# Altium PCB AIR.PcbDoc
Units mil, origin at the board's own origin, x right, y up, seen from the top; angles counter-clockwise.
Board outline 2440 x 700 mil, 2 copper layers (Top Layer, Bottom Layer); 70 components, 62 nets, 272 pads, 280 vias.
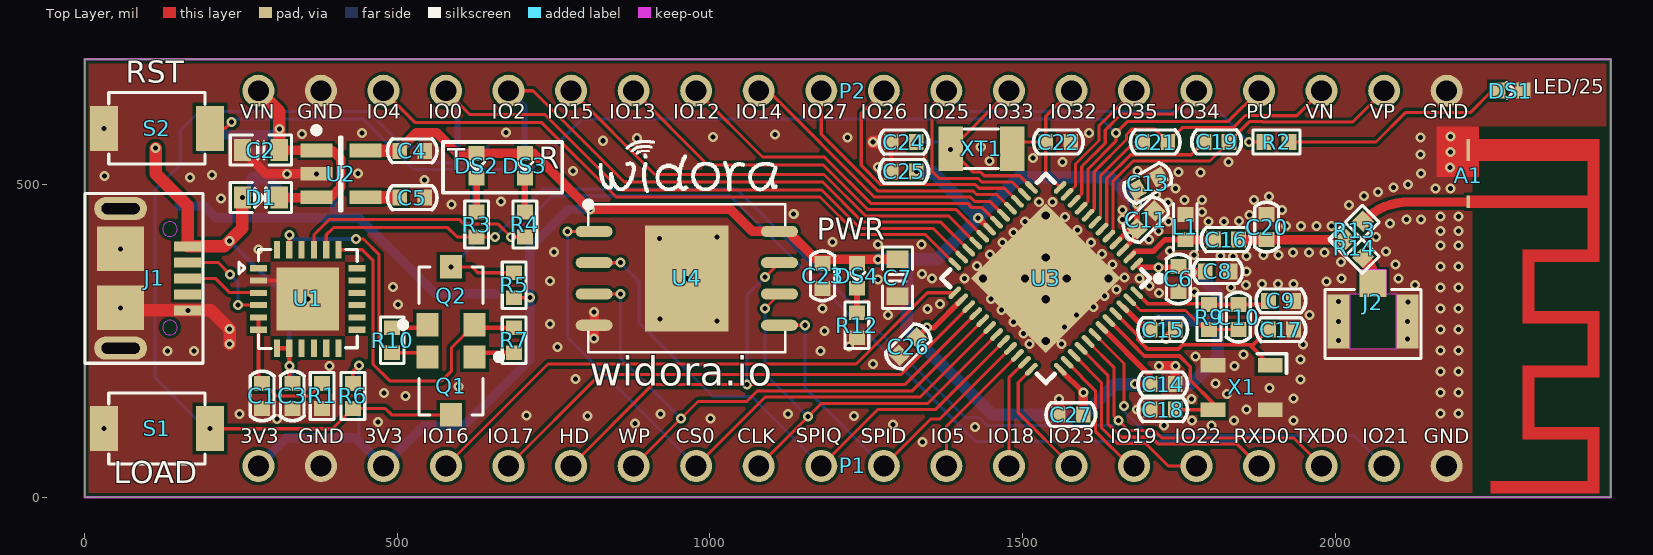
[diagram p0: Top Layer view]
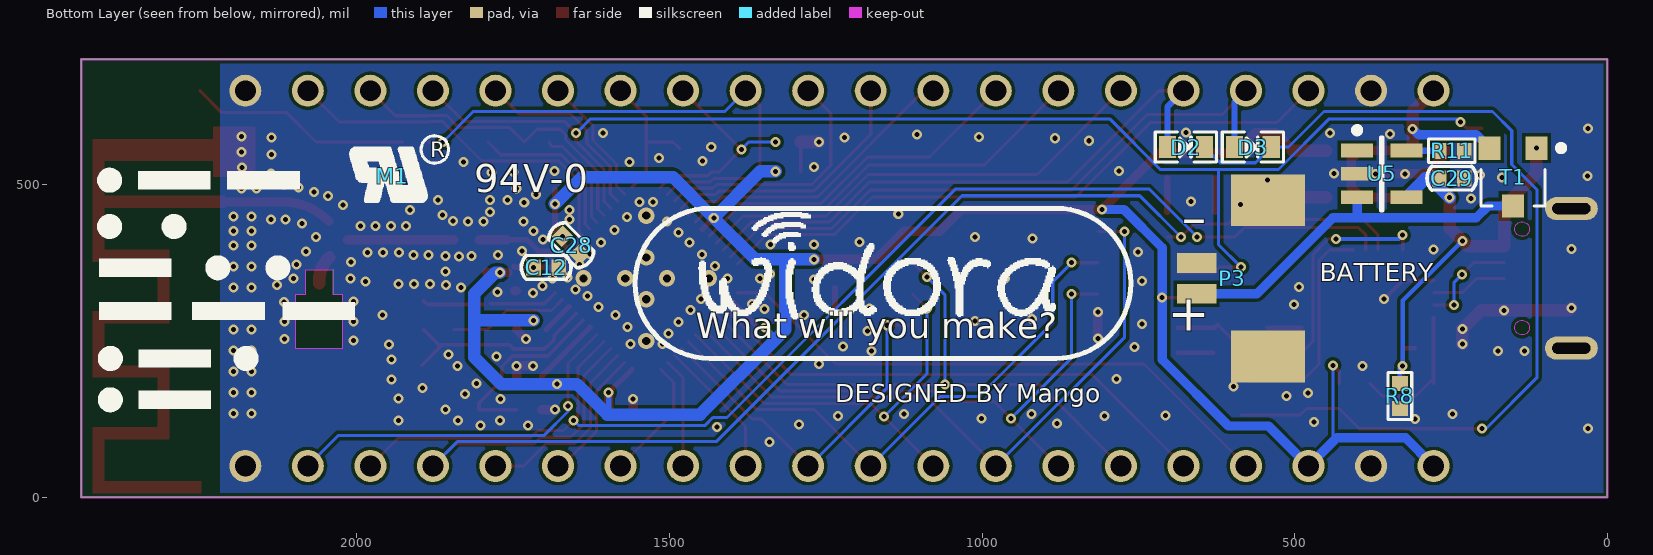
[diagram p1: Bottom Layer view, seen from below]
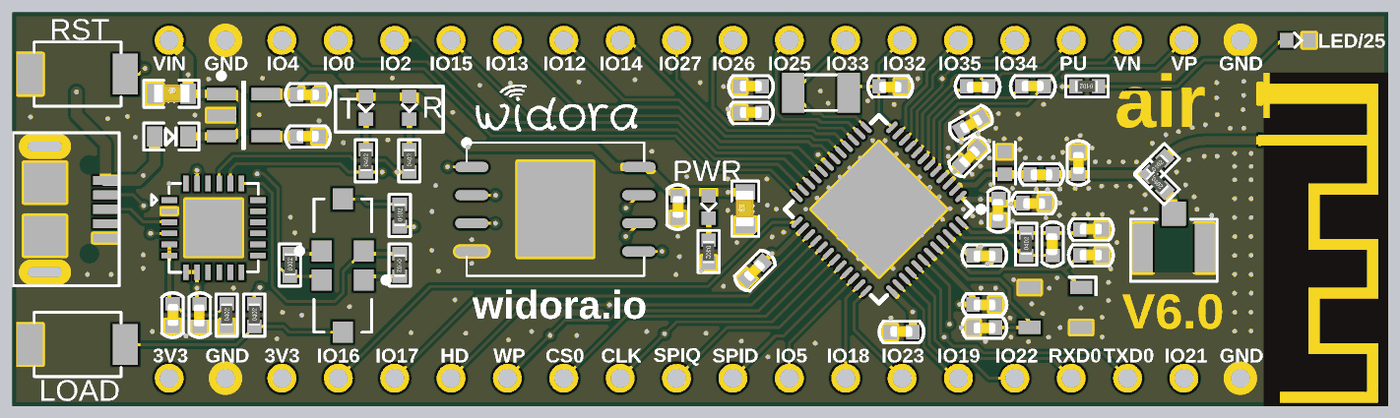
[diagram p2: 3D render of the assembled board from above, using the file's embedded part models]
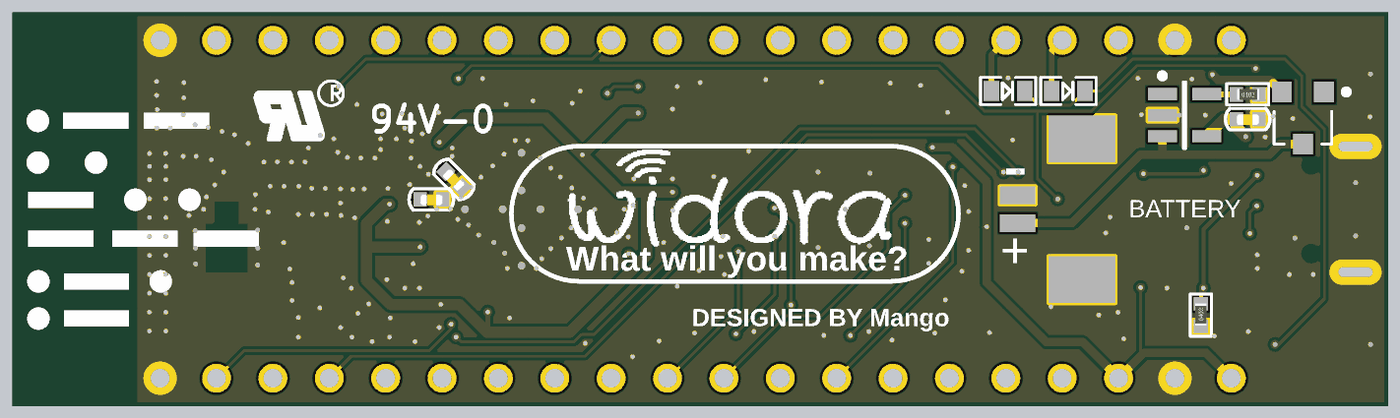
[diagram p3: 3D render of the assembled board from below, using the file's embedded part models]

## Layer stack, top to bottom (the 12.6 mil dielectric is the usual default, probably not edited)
Top Solder: solder mask 0.4, Solder Resist, Dk 3.5
Top Layer: signal copper 1.4
Dielectric1: dielectric 12.6, FR-4, Dk 4.8
Bottom Layer: signal copper 1.4
Bottom Solder: solder mask 0.4, Solder Resist, Dk 3.5

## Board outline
0,0 2440,0 2440,700 0,700

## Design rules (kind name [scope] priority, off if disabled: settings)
Clearance Clearance_1 [InPolygon] p1: gap=5
Clearance [All] p2: gap=5
ComponentClearance [All] p1 off: gap=10 collisioncheckmode=3 verticalgap=10 showdistances=FALSE
DiffPairsRouting [All] p1: maxlimit=10 minlimit=10 mostfreqgap=10 toplayer_minwidth=15 toplayer_maxwidth=15 toplayer_prefwidth=15 bottomlayer_minwidth=15 bottomlayer_maxwidth=15 bottomlayer_prefwidth=15 maxuncoupledlength=500
FabricationTestPointUsage TestPointUsage [All] p1 off: valid=0 allowmultiple=FALSE
FabricationTestpoint Testpoint [All] p1 off: side=3 testpointundercomponent=TRUE minsize=40 maxsize=100 preferedsize=60 minholesize=0 maxholesize=40 preferedholesize=32 testpointgrid=1 allowsidetop=TRUE allowsidebottom=TRUE usegrid=TRUE gridtolerance=0.01
Height [All] p1 off: minheight=0 maxheight=1000 prefheight=500
HoleToHoleClearance [All] p1: gap=6 allowstackedmicrovias=TRUE
MinimumSolderMaskSliver [All] p1: minsoldermaskwidth=1
NetAntennae [All] p1: netantennaetolerance=4
PlaneConnect [All] p1: planeconnectstyle=Direct reliefexpansion=20 reliefentries=4 reliefconductorwidth=10 reliefairgap=10
PolygonConnect [All] p1: connectstyle=Direct reliefconductorwidth=10 reliefentries=4 polygonreliefangle="90 Angle" airgapwidth=10
RoutingVias [All] p1: holewidth=8 width=16 viastyle="Through Hole" minholewidth=8 minwidth=16 maxholewidth=28 maxwidth=50
SilkToSilkClearance [All] p1: silktosilkclearance=0
SilkToSolderMaskClearance SilkscreenOverComponentPads [IsPad] p1: minsilkscreentomaskgap=0 clearancetoexposedcopper=TRUE
SolderMaskExpansion [All] p1: expansion=4
Width [All] p1: maxlimit=30 minlimit=5 preferedwidth=6
18 further rules are at their usual default settings.

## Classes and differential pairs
differential pair U: +U_P -U_N

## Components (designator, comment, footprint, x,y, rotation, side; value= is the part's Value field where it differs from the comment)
A1 "WIFI天线" 2.4G 2210,573 r270 top locked
C1 "1uF" C0402 284.02,162 r270 top
C2 "4.7uF" C0603 282,555 r0 top
C3 "1uF" C0402 332.22,162 r90 top
C4 "0.1uF" C0402 524,554 r180 top
C5 "470pF" C0402 524,479 r0 top
C6 "100pF" C0402 1749,349 r90 top
C7 "4.7uF" C0603 1300,350.94 r90 top
C8 "0.1uF" C0402 1812,361 r180 top
C9 "10nF" C0402 1913,314 r0 top
C10 "3nF" C0402 1845,288 r90 top
C11 "100pF" C0402 1697.05,443.68 r225 top
C12 "0.1uF" C0402 1697,367.5 r0 bottom
C13 "1uF" C0402 1700,502 r210 top
C14 "0.1uF" C0402 1724,181 r180 top locked
C15 "100pF" C0402 1724,267.96 r180 top
C16 "6.9pF" C0402 1825,412 r180 top
C17 "15pF" C0402 1913,268 r0 top
C18 "15pF" C0402 1724,140 r180 top locked
C19 "270pF" C0402 1810,568.04 r0 top
C20 "2.4pF" C0402 1890,432 r270 top
C21 "270pF" C0402 1712,568 r180 top
C22 "15pF" C0402 1557,568 r180 top
C23 "0.1uF" C0402 1180,353.94 r270 top
C24 "15pF" C0402 1310,568 r0 top
C25 "0.1uF" C0402 1310,521 r0 top
C26 "0.1uF" C0402 1317,241 r45 top
C27 "0.1uF" C0402 1577,132 r0 top
C28 "0.1uF" C0402 1657,403 r45 bottom
C29 "0.1uF" C0402 249,510 r0 bottom
D1 "1N5819 0603" SOD523 282,479 r0 top
D2 "1N5819 0603" SOD523 674,560 r180 bottom
D3 "1N5819 0603" SOD523 567,560 r180 bottom
DS1 "BLUE" LED0402 2280,650 r0 top
DS2 "YELLOW" LED0402 627,530 r270 top
DS3 "GREEN" LED0402 704,530 r270 top
DS4 "BLUE" LED0402 1235,354 r270 top
J1 "MK5P microUSB" MICROUSB 95,350 r270 top locked
J2 "ipex" "I-PEX SOCKET" 2060,281 r180 top locked
L1 "1.6nH" L0402 1760,432 r270 top
M1 "mark" ZY_UR-3X2 1943,513 r180 bottom locked
P1 "Header 20" HDR1X20-M2 278,50 r0 top locked
P2 "Header 20" HDR1X20-M2 278,650 r0 top locked
P3 "BATT" PH1.25-T 657,350 r90 bottom locked
Q1 "9014" SOT23 586,178 r180 top
Q2 "9014" SOT23 586,322 r0 top locked
R1 "1K" R0402 380,162 r90 top
R2 "5.1K" R0402 1906,568.02 r180 top
R3 "5.1K" R0402 627,436 r90 top
R4 "5.1K" R0402 704,436 r90 top
R5 "5.1K" R0402 687,339 r90 top
R6 "5.1K" R0402 429,162 r90 top
R7 "5.1K" R0402 687,251 r270 top
R8 "5.1K" R0402 332,162 r90 bottom
R9 "20K" R0402 1798,288 r90 top
R10 "5.1K" R0402 492,251 r90 top
R11 "3.3K" R0402 249,554 r180 bottom
R12 "5.1K" R0402 1235,275 r270 top
R13 "0R" R0402 2030.05,426.81 r45 top locked
R14 "0R" R0402 2030,398 r315 top locked
S1 "SW-BUTTON" MINIBUTTON 116,110 r180 top locked
S2 "SW-BUTTON" MINIBUTTON 116,590 r180 top locked
T1 "AO3401" SOT23 151,512 r0 bottom
U1 "CP2104" QFN24 357,317 r0 top locked
U2 "MIC5219-3.3" SOT23-5 410,517 r0 top
U3 "ESP32" QFN40P600X600X100-48N 1537,350 r225 top locked
U4 "W25Q32" WSON-SPIFLASH 963,350 r0 top locked
U5 "LTC4054" SOT23-5 361,517 r180 bottom
X1 "40MHz-3225" XTAL3225 1850,176 r0 top locked
XT1 "32.768K-3215" Y3215 1434,557 r0 top

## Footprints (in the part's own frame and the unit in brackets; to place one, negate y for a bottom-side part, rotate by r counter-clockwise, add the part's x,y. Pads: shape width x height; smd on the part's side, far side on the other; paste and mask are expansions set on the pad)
2.4G [mil]
  rect 20x5 smd paste-39.37: 1(100.4,2.5)
  rect 35.43x5 smd paste-39.37: 2(17.72,2.5)
  Top Layer region: 0,0 35.43,0 35.43,194.88 0,194.88
  Top Layer region: 90.55,0 110.24,0 110.24,194.88 90.55,194.88
  Top Layer region: 547.24,37.79 566.93,37.79 566.93,194.88 547.24,194.88
  Top Layer region: 460.63,193.04 566.93,193.04 566.93,212.72 460.63,212.72
  Top Layer region: 460.63,88.98 480.31,88.98 480.31,194.88 460.63,194.88
  Top Layer region: 379.92,88.98 462.6,88.98 462.6,108.66 379.92,108.66
  Top Layer region: 362.2,88.98 381.89,88.98 381.89,194.88 362.2,194.88
  Top Layer region: 275.59,193.04 381.89,193.04 381.89,212.72 275.59,212.72
  Top Layer region: 275.59,88.98 295.28,88.98 295.28,194.88 275.59,194.88
  Top Layer region: 194.88,89.1 277.56,89.1 277.56,108.78 194.88,108.78
  Top Layer region: 177.16,88.98 196.85,88.98 196.85,194.88 177.16,194.88
  Top Layer region: 0.12,192.91 196.97,192.91 196.97,212.6 0.12,212.6
C0402 [mm]
  rect 0.6x0.65 smd: 1(-0.508,0) 2(0.508,0)
  silkscreen extent -1.01,-0.48 1.01,0.48, body extent -0.51,-0.23 0.49,0.27, height 0.5
C0603 [mm]
  rect 0.7x0.9 smd: 1(-0.75,0) 2(0.75,0)
  silkscreen extent -1.24,-0.61 1.24,0.61, body extent -0.79,-0.38 0.81,0.42, height 0.3
HDR1X20-M2 [mm]
  round 1.3 hole 0.85: 1(0,0) 2(2.54,0) 3(5.08,0) 4(7.62,0) 5(10.16,0) 6(12.7,0) 7(15.24,0) 8(17.78,0) 9(20.32,0) 10(22.86,0) 11(25.4,0) 12(27.94,0) 13(30.48,0) 14(33.02,0) 15(35.56,0) 16(38.1,0) 17(40.64,0) 18(43.18,0) 19(45.72,0) 20(48.26,0)
"I-PEX SOCKET" [mm]
  rect 1.1x1.1 smd: 1(0,-1.55)
  rect 0.9x2.2 smd: 2(1.4,0) 3(-1.4,0)
  Keep-Out Layer pour cut-out: -0.95,1.1 -0.95,-1.101 -0.551,-1.101 -0.551,-2.101 0.001,-2.101 0.55,-2.101 0.55,-1.101 0.95,-1.101 0.95,1.1
  silkscreen extent -1.95,-1.3 1.95,1.5
L0402 [mm]
  rect 0.6x0.65 smd: 1(-0.508,0) 2(0.508,0)
  silkscreen extent -0.95,-0.48 0.95,0.48
LED0402 [mm]
  rect 0.6x0.65 smd: A(-0.508,0) K(0.508,0)
  silkscreen extent -0.15,-0.32 0.18,0.33
MICROUSB [mm] "MICROUSB"
  rect 0.4x1.1 smd: 1(-1.3,1.78) 2(-0.65,1.78) 3(0,1.78) 4(0.65,1.78) 5(1.3,1.78)
  oval 0.94x2.15 hole 0.45 slot 1.55 at 90 deg: 6(-2.835,-0.946) 7(2.835,-0.946)
  rect 1.8x1.9 smd: 8(-1.2,-0.946) 9(1.2,-0.946)
  Keep-Out Layer circle w0.025: c-2,1.054 r0.3
  Keep-Out Layer circle w0.025: c2,1.054 r0.3
  silkscreen extent -3.45,-2.4 3.45,2.4
MINIBUTTON [mil] "MINIBUTTON"
  rect 44.88x72.05 smd: 1(-84.42,0.08) 2(84.88,0.08)
  silkscreen extent -77,-57 77,57
PH1.25-T [mm] "2.0 tie"
  rect 2.1x3 smd: 0(-3.175,-2.9) 0(3.175,-2.9)
  rect 0.8x1.6 smd: 1(0.625,0) 2(-0.625,0)
QFN24 [mm]
  rect 0.7x0.25 smd: 1(-2,1.25) 2(-2,0.75) 3(-2,0.25) 4(-2,-0.25) 5(-2,-0.75) 6(-2,-1.25) 13(2,-1.25) 14(2,-0.75) 15(2,-0.25) 16(2,0.25) 17(2,0.75) 18(2,1.25)
  rect 0.25x0.7 smd: 7(-1.25,-2) 8(-0.75,-2) 9(-0.25,-2) 10(0.25,-2) 11(0.75,-2) 12(1.25,-2) 19(1.25,2) 20(0.75,2) 21(0.25,2) 22(-0.25,2) 23(-0.75,2) 24(-1.25,2)
  rect 2.55x2.55 smd: 25(0,0)
  silkscreen extent -2.79,-2.01 2.01,2.01
QFN40P600X600X100-48N [mm] "QFN, 48-Leads, Body 6.0x6.0mm (max), Pitch 0.40mm, IPC Medium Density"
  oval 0.65x0.2 smd: 1(-3.025,2.2) 2(-3.025,1.8) 3(-3.025,1.4) 4(-3.025,1) 5(-3.025,0.6) 6(-3.025,0.2) 7(-3.025,-0.2) 8(-3.025,-0.6) 9(-3.025,-1) 10(-3.025,-1.4) 11(-3.025,-1.8) 12(-3.025,-2.2) 25(3.025,-2.2) 26(3.025,-1.8) 27(3.025,-1.4) 28(3.025,-1) 29(3.025,-0.6) 30(3.025,-0.2) 31(3.025,0.2) 32(3.025,0.6) 33(3.025,1) 34(3.025,1.4) 35(3.025,1.8) 36(3.025,2.2)
  oval 0.2x0.65 smd: 13(-2.2,-3.025) 14(-1.8,-3.025) 15(-1.4,-3.025) 16(-1,-3.025) 17(-0.6,-3.025) 18(-0.2,-3.025) 19(0.2,-3.025) 20(0.6,-3.025) 21(1,-3.025) 22(1.4,-3.025) 23(1.8,-3.025) 24(2.2,-3.025) 37(2.2,3.025) 38(1.8,3.025) 39(1.4,3.025) 40(1,3.025) 41(0.6,3.025) 42(0.2,3.025) 43(-0.2,3.025) 44(-0.6,3.025) 45(-1,3.025) 46(-1.4,3.025) 47(-1.8,3.025) 48(-2.2,3.025)
  rect 4.3x4.3 smd: 49(0,0)
  silkscreen extent -3.37,-3 3,3.38, body extent -3,-3 3,3, height 1
R0402 [mm]
  rect 0.6x0.65 smd: 1(-0.508,0) 2(0.508,0)
  silkscreen extent -0.95,-0.48 0.95,0.48, body extent -0.47,-0.25 0.53,0.25, height 0.35
SOD523 [mm]
  rect 0.7x0.9 smd: A(-0.75,0) K(0.75,0)
  silkscreen extent -1.24,-0.61 1.24,0.61
SOT23 [mm] "SOT-23; 3 Leads; Body 3.0 x 2.5 mm, inc. leads (LxW max)"
  rect 0.9x0.95 smd: 1(-0.95,-1.175) 2(0.95,-1.175) 3(0,1.175)
  silkscreen extent -2.07,-1.3 1.3,1.18
SOT23-5 [mm] "SOT23, 5-Leads, Body 3.0x2.6mm (max), Pitch 0.95mm, IPC Medium Density"
  rect 1.3x0.55 smd: 1(-1,0.95) 2(-1,0) 3(-1,-0.95) 4(1,-0.95) 5(1,0.95)
  silkscreen extent -1.12,-1.5 0.05,1.9, body extent -0.7,-1.5 0.7,1.5, height 1.1
WSON-SPIFLASH [mm]
  oval 1.5x0.45 smd: 1(-3.764,1.905) 2(-3.764,0.635) 3(-3.764,-0.635) 4(-3.764,-1.905) 5(3.764,-1.905) 6(3.764,-0.635) 7(3.764,0.635) 8(3.764,1.905)
  rect 3.4x4.3 smd: 4(0,0)
  silkscreen extent -4.12,-3 4,3.12
XTAL3225 [mm] "XTAL3225"
  rect 1x0.6 smd: 1(1.16,0.887) 2(-1.16,0.887) 3(-1.16,-0.913) 4(1.16,-0.913)
  silkscreen extent 0.64,0.57 1.83,1.36
Y3215 [mm]
  rect 1x1.8 smd: 1(-1.25,0) 2(1.25,0)
  silkscreen extent -0.7,-0.8 0.7,0.8
ZY_UR-3X2 [mil]
  silkscreen extent -67,-40 90,65

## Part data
A1: library part ANT2.4G
C1 C2 C3 C4 C5 C6 C7 C8 C9 C10 C11 C12 C13 C14 C15 C17 C18 C19 C21 C22 C23 C24 C25 C26 C27 C28 C29: library part CAP, "普通小电容"
C16 C20: library part CAP, "射频电容"
D1 D2 D3: library part Diode, "普通二极管"
DS1 DS2 DS3 DS4: library part LED, "LED"
J1: library part MICRO_USB, "4固定脚microUSB座"
J2: library part MCX_IPEX
L1: library part L0402, "射频电感"
P1 P2: "Header, 20-Pin"
P3: library part "Header 2T", "Header, 4-Pin"
Q1 Q2: library part NPN, "NPN三极管"
R1 R2 R3 R4 R5 R6 R7 R8 R9 R10 R11 R12 R13 R14: library part RES, "普通电阻"
T1: library part MOS-P
U2: library part MIC5219
U4: library part SPIFLASH_SOP8W
U5: "锂电池管理芯片"
X1: library part XTAL3225
XT1: library part XT, "晶振"

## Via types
v1: diameter 16, hole 8, Top Layer to Bottom Layer, tented both sides, 272 vias
v2: diameter 25.98, hole 12.99, Top Layer to Bottom Layer, tented both sides, 8 vias

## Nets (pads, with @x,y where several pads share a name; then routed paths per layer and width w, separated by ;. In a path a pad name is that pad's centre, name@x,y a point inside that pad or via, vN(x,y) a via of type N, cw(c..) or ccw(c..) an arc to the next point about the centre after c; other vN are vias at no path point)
CHIP_PU: P2.17 Q2.3 R5.2 S2.1 U3.9 | length 2207.3
  Top Layer w5: S2.1 224.92,589.92 v1(235,600) ; v1(586,368.26) 619.46,368.26 628.72,359 R5.2 ; U3.9 1604.48,473.16 1604.48,524.62 1649,569.14 v1(1649,582) 1668,601 1829,601 P2.17
  Bottom Layer w5: v1(235,600) 236,600 241,605 445,605 526,524 622,524 ; v1(586,368.26) 586.34,368.26 622,403.92 622,524 ; v1(1649,582) 1626,605 796,605 715,524 622,524
DL: D2.K D3.K Q1.3 R6.1 S1.1 | length 1484.6
  Top Layer w5: v1(200.42,109.92) 200.84,109.5 396.5,109.5 R6.1 480.74,142 491,131.74 Q1.3
  Bottom Layer w5: v1(200.42,109.92) 194.08,109.92 113,191 113,492 153,532 153,586 183.74,616.74 453.26,616.74 510,560 D3.K 562.69,534.78 619.26,534.78 D2.K
DTR: Q1.2 R10.1 U1.23 | length 403.5
  Top Layer w5: v1(434,413) 446,413 471,388 471,249 R10.1@489,231 ; R10.1 541.86,231 Q1.2
  Top Layer w6: U1.23 v1(327.47,419)
  Bottom Layer w6: v1(327.47,419) 333.47,413 v1(434,413)
GND: A1.2 C1.2 C2.1 C3.1 C4.1 C5.2 C6.1 C7.1 C8.1 C9.2 C11.1 C12.1 C13.1 C14.1 C15.1 C17.2 C18.2 C20.1 C22.1 C23.2 C24.1 C25.1 C26.1 C27.1 C28.1 C29.1 DS1.K J1.5 J1.6 J1.7 J1.8 J1.9 J2.2 J2.3 L1.1 P1.2 P1.20 P2.2 P2.20 P3.0 P3.1 R1.1 R8.1 R11.2 R12.2 S1.2 S2.2 U1.2 U1.25 U2.2 U3.49 U4.4 U5.2 X1.2 X1.4 | length 682.6
  Top Layer w6: C25.1 C24.1 ; v1(1347.59,301) v1@1352,301
  Top Layer w7: U1.2 327.47,346.53 v1(357,317)
  Top Layer w15: C2.1 290.47,517 v1(370.63,517) ; v1(814.81,254) 814.81,275 v1(814.81,296) ; C27.1@1558,133 v1(1558,157) ; v1(1683,140) C18.2 ; v1(1718,210) v1(1744,210) C14.1 ; v1(1729.32,253.27) C15.1 ; C6.1@1744.72,330 C6.1@1747,330
  Top Layer w20: v1(57.74,302.75) 61.39,299.1 164.8,299.1 v1(165.09,298.81) 202.19,298.81 v1(232,269) v1(232,245) ; v1(1261,568) C24.1
  other v1: 1340,88 31.12,109.92 1424,112 1726,115 1802,115 1293,116 880,118 469,120 1771,123 1838,123 1933,123 308,125 1001,126 804,130 1230,130 707,131 248,133 921,133 1125,133 2168,133.6 2197,133.6 1858,140 1770,157 1933,158 513,162 1827,165 479,167 2168,167.2 2197,167.2 1895,175 598,177 1808,182 1944,188 785,189 2168,200.8 2197,200.8 392,210 1839,210 1261,213 1944,220 1776,225 1853,228 133,234 175,234 1177,234 2168,234.4 2197,234.4 756,240 1222,241 1948,244 1511,245 1562,245 2005,251 2115,253 1501,262 1183,266 2168,268 2197,268 1567,272 744,277 1485,280 2004.88,281 2115.12,281 1011,282 920,285 1285,291 1586,291 1959,291 1466,299 1180,302 2168,301.6 2197,301.6 1613,304 501,308 1368,309 2116,312 2005,313 1449,317 1631,322 1718.18,326.74 1775,328.4 1650,332 1833,335 2168,335.2 2197,335.2 493,336 1703,338 1857,339 2127,339 1883,341 1908,341 1933,341 1986,345 744,346 1269,348 963,350 1355,350 1407,350 1687,350 2010,350 2101,350 1663,351 1339,357 1858,361 2168,368.8 2197,368.8 1427,370 1644,372 2096,372 2009,376 1836,385 1816,386 1858,386 1774,387 1885,387 1909,387 1448,388 1627,389 1932,391 1958,391 1983,391 751,392 2081,393 1735.35,393.9 278.26,395.74 57.74,397.23 2168,402.4 2197,402.4 1269,404 1338,404 1468,407 1609,407 1196,408 1702,412 919,414 1011,416 2065,416 1485,423 1717,426 2168,426 2197,426 1588,427 1921,434 1945,434 1970,434 1994,434 2087,438 1504,441 1733,441 1797,441 1822,441 1846,442 1660,444 2114,444 2137,444 1568,448 2168,449 2197,449 1863,451 1134,453 1787,456 1660,459 1915,459 2022,467 587,468 1732,471 1526,472 1548,472 666,473 1759,475 1787,475 1870,475 218,478 1894,481 2046,482 1713,484 2068,488 1744,494 2160,494 2184,494 2093,495 2116,500 544,507 169,511 32,514 204,515 324,517 437.56,518 2137,518 1784,519 1749,520 781,522 1684,522 2183,527 1269,528 1564,536 1829,536 1447,538 1516.87,542.37 2136,548 2184,552 1433,560 829,570 883,574 1220,575 2136,575 1005,576 2184,577 1104,580 348,581 1606,582 443.63,582.53 674,583 31.12,589.92
  other v2: 1537,249.78 1537,316.59 1436.78,350 1503.59,350 1570.41,350 1637.22,350 1537,383.41 1537,450.22
GPI34: P2.16 U3.10 | length 306.5
  Top Layer w5: U3.10 1594.48,485.43 1594.48,528.77 1632,566.28 1632,587 1658,613 1741,613 P2.16
GPI35: P2.15 U3.11 | length 210
  Top Layer w5: U3.11 1584.48,497.7 1584.48,532.91 1622,570.43 1622,594 P2.15
GPIO0: D3.A P2.4 U3.23 | length 1032.5
  Top Layer w5: P2.4 616,612 736,612 857,491 1179.14,491 1240.33,429.81 1356.97,429.81 U3.23
  Bottom Layer w10: P2.4 596.53,631.47 D3.A
GPIO2: D2.A P2.5 U3.22 | length 946.9
  Top Layer w5: P2.5 717,650 863,504 1180.28,504 1244.48,439.81 1369.24,439.81 U3.22
  Bottom Layer w10: P2.5 703.53,624.47 D2.A@703.53,555
GPIO4: P2.3 U3.24 | length 1028.3
  Top Layer w5: P2.3 529,599 731,599 850,480 1176,480 1236.19,419.81 1344.7,419.81 U3.24
GPIO5: P1.12 U3.34 | length 223.9
  Top Layer w5: P1.12 1378,99 1378,113.05 U3.34
GPIO12: P2.8 U3.18 | length 567.4
  Top Layer w5: P2.8 1084,544 1182.71,544 1256.9,469.81 1412.07,469.81 1418.88,463 1435.14,463 U3.18
GPIO13: P2.7 U3.20 | length 654.4
  Top Layer w5: P2.7 997,531 1181.57,531 1252.76,459.81 1393.79,459.81 U3.20
GPIO14: P2.9 U3.17 | length 474
  Top Layer w5: P2.9 1093,650 1263.19,479.81 1416.21,479.81 1423.02,473 1447.41,473 U3.17
GPIO15: P2.6 U3.21 | length 747.9
  Top Layer w5: P2.6 912,516 1182.43,516 1248.62,449.81 1381.52,449.81 U3.21
GPIO16: P1.4 U3.25 | length 928.3
  Top Layer w5: P1.4 741,213 1233.69,213 1347.73,327.03 U3.25
GPIO17: P1.5 U3.27 | length 841.3
  Top Layer w5: P1.5 824,196 1305.05,196 U3.27
GPIO18: P1.13 U3.35 | length 176
  Top Layer w5: P1.13 1478,190.78 U3.35
GPIO19: P1.15 U3.38 | length 213.5
  Top Layer w5: U3.38 1616.31,170.47 1616.31,105.69 1672,50 P1.15
GPIO21: P1.19 U3.42 | length 594.5
  Top Layer w5: U3.42 1662,213.86 v1(1662,146)
  Bottom Layer w5: v1(1662,146) 1662,137 1700,99 2029,99 P1.19
GPIO22: P1.16 U3.39 | length 311.2
  Top Layer w5: U3.39 1626.31,182.74 1626.31,110.69 1651,86 1697,86 1733,50 P1.16
GPIO23: P1.14 U3.36 | length 198.5
  Top Layer w5: U3.36 1493,183.51 1493,135 P1.14
GPIO25: P2.12 R2.2 U3.14 | length 843.6
  Top Layer w5: P2.12 1355,627 1355,521 1366.19,509.81 1428.64,509.81 1434.38,504.07 1483.15,504.07 U3.14 ; v1(1862.02,568.02) R2.2
  Bottom Layer w5: P2.12 1411.09,616.91 1813.13,616.91 v1(1862.02,568.02)
GPIO26: P2.11 U3.15 | length 407.9
  Top Layer w5: P2.11 1242,614 1242,530.55 1272.74,499.81 1424.5,499.81 1430.3,494 1470.95,494 U3.15
GPIO27: P2.10 U3.16 | length 421.2
  Top Layer w5: P2.10 1178,580.4 1268.6,489.81 1420.35,489.81 1426.16,484 1458.68,484 U3.16
GPIO32: C22.2 P2.14 U3.12 XT1.2 | length 239.4
  Top Layer w5: XT1.2 1494.21,568 C22.2 ; U3.12 1537,518.42 C22.2 ; P2.14 1537,609 C22.2
GPIO33: C24.2 P2.13 U3.13 XT1.1 | length 362.2
  Top Layer w5: XT1.1@1373.79,568 XT1.1 ; P2.13 1478,649.21 v1(1384.79,556) 1420.98,519.81 1432.78,519.81 1438.52,514.07 1495.42,514.07 U3.13
  Bottom Layer w5: v1(1330,568) 1372.79,568 v1(1384.79,556)
NetA1_1: A1.1 R13.2 | length 176.9
  Top Layer w15: R13.2 2045.95,442.71 cw(c2116.66,372) 2116.66,472 A1.1@2212.5,472
NetC1_1: C1.1 R1.2 U1.5 U1.6 | length 220.3
  Top Layer w5: C1.1@282.82,185.8 306.93,161.68 359.68,161.68 R1.2
  Top Layer w7: C1.1@278.26,182.76 U1.6 U1.5
NetC5_1: C5.1 U2.4 | length 54
  Top Layer w20: U2.4 C5.1@503.4,479.6
NetC9_1: C9.1 C10.2 R9.2 U3.48 | length 208.6
  Top Layer w6: U3.48 1700.3,309.19 1765.11,309.19 R9.2@1786.19,309.19 ; R9.2 C10.2 1887,308 C9.1
NetC10_1: C10.1 R9.1 U3.47 | length 203.9
  Top Layer w5: U3.47 1688.53,298.69 1760.31,298.69 1791,268 R9.1 C10.1
  Top Layer w6: U3.47@1671.68,315.9 U3.47 U3.47@1678.39,308.83
NetC16_1: C16.1 C20.2 R13.1 R14.1 | length 170
  Top Layer w15: C16.1 R13.1@2015,412
NetC17_1: C17.1 U3.45 X1.1 | length 330.9
  Top Layer w6: U3.45 1649.05,293.27 1684.19,258.13 1684.19,251.85 1688.88,247.16 1689.41,247.16 1699.57,237 1748.96,237 1755.96,244 1862.6,244 ; C17.1 1869,244 1862.6,244 ; X1.1 1862.6,244
NetC18_1: C18.1 U3.44 X1.3 | length 304.9
  Top Layer w6: U3.44 1638.53,282.49 1673.19,247.83 1673.19,247.29 1694.48,226 1750.63,226 1768,208.63 1768,187 1804.33,150.67 X1.3 C18.1@1744,140.07
NetC19_1: C19.1 U3.6 | length 263.9
  Top Layer w5: U3.6 1634.48,436.35 1634.48,509.62 1672.56,547.7 1769.66,547.7 C19.1
NetC21_2: C21.2 U3.7 | length 168.8
  Top Layer w5: U3.7 1624.48,448.62 1624.48,513.77 1671.72,561 1688,561 C21.2
NetDS1_A: DS1.A R2.1 | length 358.4
  Top Layer w5: R2.1 2065.02,568.02 2112,615 2215.47,615 DS1.A@2250.47,650
NetDS2_K: DS2.K R3.2 | length 54
  Top Layer w10: R3.2 DS2.K
NetDS3_K: DS3.K R4.2 | length 54
  Top Layer w10: R4.2 DS3.K
NetDS4_K: DS4.K R12.1 | length 39
  Top Layer w10: R12.1 DS4.K
NetJ2_1: J2.1 R14.2 | length 46.1
  Top Layer w20: R14.2 cw(c2005.86,345.57) 2060,345.57 J2.1
NetQ1_B: Q1.1 R7.2 | length 56.9
  Top Layer w7: Q1.1@630.14,231 R7.2
NetQ2_B: Q2.1 R10.2 | length 54.9
  Top Layer w7: R10.2@489,271 Q2.1@543.86,271
NetR11_1: R11.1 U5.5 | length 52.2
  Bottom Layer w10: R11.1 U5.5@321.23,554
RF: C16.2 L1.2 U3.2 | length 145.9
  Top Layer w9: U3.2 1680.72,393.5 1709.25,393.5 1727.75,412 L1.2@1758,412 ; L1.2@1756.81,413.19 L1.2@1758,412 ; L1.2 L1.2@1758,412
  Top Layer w15: L1.2 C16.2@1804,412
RTS: Q2.2 R7.1 U1.19 | length 525.9
  Top Layer w5: U1.19 444.26,395.74 461,379 461,213 488,186 571,186 587,202 587,239.34 Q2.2
  Top Layer w7: Q2.2 628.14,271 R7.1
RXD0: P1.17 R4.1 U1.21 U3.40 | length 2192.9
  Top Layer w5: U1.21 366.84,419.5 391.6,444.26 599.14,444.26 606.7,436.69 661.31,436.69 v1(682,416) R4.1 ; U3.40 1636.31,195.01 1636.31,117.69 1658,96 1706,96 1717,85 1843,85 P1.17
  Bottom Layer w5: v1(682,416) 748,482 1032.08,482 1425.08,89 1839,89 P1.17
SENS_VN: C21.1 P2.18 U3.8 | length 507
  Top Layer w5: U3.8 1614.48,460.89 1614.48,520.48 1666,572 1666,580 1674.3,588.3 1711.7,588.3 C21.1 ; C21.1@1735.61,571.61 1755,591 1836.86,591 1856.36,610.5 1887.56,610.5 ; 1888.06,610 1938,610 P2.18
SENS_VP: C19.2 P2.19 U3.5 | length 584.5
  Top Layer w5: U3.5 1644.48,424.07 1644.48,505.48 1676.7,537.7 1799.66,537.7 C19.2 1862.46,600.5 1875.39,600.5 1883.42,600.5 1883.92,600 2028,600 P2.19
SPICLK: P1.9 U3.31 U4.6 | length 701.8
  Top Layer w5: P1.9 v1(1156.74,128.74) 1178,150 1348.14,150 U3.31 ; v1(1088,301.81) U4.6
  Bottom Layer w5: v1(1088,301.81) 1088,197.47 v1(1156.74,128.74)
SPICS0: P1.8 U3.30 U4.1 | length 1064.3
  Top Layer w5: v1(772,425.19) 772.19,425 U4.1 ; P1.8 1088,160 1335.86,160 U3.30
  Bottom Layer w5: v1(772,425.19) 772,256 P1.8
SPID: P1.11 U3.33 U4.5 | length 597.8
  Top Layer w5: U4.5 v1(1152.19,275) ; P1.11 1353,125 1367.68,125 U3.33
  Bottom Layer w5: v1(1152.19,275) 1152.19,174 P1.11@1276.19,50
SPIHD: P1.6 U3.28 U4.7 | length 964.5
  Top Layer w5: P1.6 908,180 v1(1059,180) 1311.32,180 U3.28 ; v1(1088.31,352.12) U4.7
  Bottom Layer w5: v1(1059,180) 1059,322.81 v1(1088.31,352.12)
SPIQ: P1.10 U3.32 U4.2 | length 910.3
  Top Layer w5: U4.2 v1(856.81,375) ; P1.10 1268,140 1360.41,140 U3.32
  Bottom Layer w5: v1(856.81,375) 887,344.81 887,279 1004.85,161.15 1066.85,161.15 P1.10
SPIWP: P1.7 U3.29 U4.3 | length 948.8
  Top Layer w5: U4.3 v1(856.81,325) ; P1.7 981,153 1059,153 1076,170 1323.59,170 U3.29
  Bottom Layer w5: v1(856.81,325) 856.81,223 938.91,140.91 ; v1@948.31,131.5 938.91,140.91 ; v1(953.73,126.08) 938.91,140.91
TXD0: P1.18 R3.1 U1.20 U3.41 | length 1994.8
  Top Layer w5: U1.20 386.53,419.53 398,431 581,431 596,416 R3.1 v1(656,416) ; U3.41 1646.31,207.28 1646.31,129.69 v1(1653,123) 1669.29,106.71 1710.29,106.71 1722,95 1933,95 P1.18
  Bottom Layer w5: v1(656,416) 733,493 1042.25,493 1407.75,127.5 1430.42,127.5 1443.42,114.5 1644.5,114.5 v1(1653,123)
U_N: J1.2 U1.4 | length 163
  Top Layer w5: J1.2 213.42,375.58 v1(233,356) ; v1(245.16,307.16) U1.4
  Bottom Layer w5: v1(233,356) 245.16,343.84 v1(245.16,307.16)
U_P: J1.3 U1.3 | length 122.8
  Top Layer w5: J1.3 209.01,349.99 231.34,327.66 277.44,327.66 U1.3
USB5V: C3.2 C29.2 D1.A J1.1 R8.2 T1.1 U1.7 U1.8 U5.4 | length 775.4
  Top Layer w7: U1.7 U1.8 v1(327.47,210) 327.47,183.25 C3.2@326.22,182
  Top Layer w20: v1(113.6,558.26) 113.6,517.4 165.09,465.91 J1.1 223.17,401.17 v1(232,410) 252.47,430.47 v1(252.47,479)
  Bottom Layer w7: v1(232,410) 327.47,314.53 v1(327.47,210) 332,205.47 R8.2
  Bottom Layer w20: v1(252.47,479) 269,495.53 C29.2 291.23,510 U5.4
V_BAT: P3.2 T1.3 U5.3 | length 596.4
  Bottom Layer w15: T1.3 191.26,465.74 210,447 439,447 560.61,325.39 P3.2 ; 400.37,447.37 U5.3
VCC3V3: C4.2 C6.2 C7.2 C8.2 C11.2 C12.2 C13.2 C14.2 C15.2 C23.1 C25.2 C26.2 C27.2 C28.2 DS2.A DS3.A DS4.A P1.1 P1.3 R5.1 R6.2 U2.5 U3.1 U3.3 U3.4 U3.19 U3.26 U3.37 U3.43 U3.46 U4.8 | length 4265.2
  Top Layer w6: R6.2 429,201 v1(439,211) ; C4.2@503.6,554.4 C4.2 ; R5.1 v1(712,319)
  Top Layer w8: U3.4 1671.54,428.86 C11.2@1682.86,428.86 ; U3.3 1682.91,417.96 C11.2
  Top Layer w9: C26.2 v1(1347.28,271.28) 1358.06,271.28 U3.26 ; v1(1429,446.86) U3.19 ; U3.37 v1(1597,167.51) ; U3.43 1704,194.14 C14.2 ; U3.46 C15.2@1696.99,267.96 ; U3.1 1687.93,367.5 1747.5,367.5 C6.2
  Top Layer w10: v1(1680,181) C14.2 ; C13.2 1682.86,491.82 v1(1682.86,469) C11.2
  Top Layer w12: C11.2@1682.74,428.97 C11.2@1682.86,428.86
  Top Layer w15: C4.2 504,556.28 530.72,583 563,583 596,550 DS2.A DS3.A 718,550 v1(808,460) 1033,460 1068,425 U4.8 1125,425 1169.54,380.46 v1(1269,380.46) C7.2 ; C27.2 v1(1597,167.51) ; C6.2@1758.57,359.43 1770.99,359.43 C8.2@1792,359.84
  Top Layer w20: U2.5 C4.2@503.6,554.4
  Bottom Layer w5: 439,89 v1(439,211)
  Bottom Layer w9: 1328,254.67 1330.67,254.67 v1(1347.28,271.28) ; v1(1597,167.51) 1597,134 1599,132 ; 1810.96,282.96 1812,284
  Bottom Layer w15: P1.1 323,95 433,95 439,89 P1.3 542,114 606,114 712,220 v1(712,319) 712,399 773,460 v1(808,460)
  Bottom Layer w20: v1(1269,380.46) 1315,380.46 ; v1(1330,521) 1354.86,521 v1(1429,446.86) ; v1(1682.86,469) 1639.86,512 1494.14,512 v1(1429,446.86) ; v1(1717,282.96) 1810.96,282.96 ; v1(1771,359) 1778,359 1812,325 1812,284 1812,224 1769,181 1648,181 1599,132 1450.67,132 1328,254.67 1315,267.67 1315,380.46 ; 1315,380.46 1362.6,380.46 v1(1429,446.86)
  other v1: 1717,367.5 1671.14,417.14
VIN: C2.2 D1.K P2.1 T1.2 U2.1 U2.3 | length 497.8
  Top Layer w15: D1.K U2.3@370.03,479 ; C2.2 U2.1@370.03,555 ; U2.3 393.6,479.6 410,496 410,541 396.6,554.4 U2.1
  Top Layer w20: P2.1 311.53,616.47 v1(311.53,589) C2.2
  Bottom Layer w15: T1.2 209.64,579.5 302.03,579.5 v1(311.53,589)
pads on no net: J1.4 U1.1 U1.9 U1.10 U1.11 U1.12 U1.13 U1.14 U1.15 U1.16 U1.17 U1.18 U1.22 U1.24 U5.1

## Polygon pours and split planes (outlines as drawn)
GND on Top Layer "Bottom Layer-No Net" (solid, remove dead copper, pour order 1000): 1.73,701.01 2440,701.01 2440,1.01 1.73,1.01
GND on Bottom Layer "Bottom Layer-No Net" (solid, remove dead copper, pour order 1001): 1.13,700.13 2440.41,700.13 2440.41,0.13 1.13,0.13

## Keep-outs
Keep-Out Layer:
  the board outline again, w4

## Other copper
Top Layer:
  rectangle net NetA1_1: 2184,466.6 2212.5,478
  rectangle net GND: 2162,512 2230,592.54
  pour cut-out: 1787.39,395.44 1778.98,395.44 1778,394.46 1778,399.51 1787.39,399.51
  pour cut-out: 1777.8,428.81 1786.2,428.81 1787.19,429.8 1787.19,424.74 1777.8,424.74
  pour cut-out: 1814,431 1835,431 1835,394.2 1824,394 1814,394.2
  pour cut-out: 2219,593 2433.36,593 2433.36,0.64 2219,0.64
  pour cut-out: 2013.35,389.72 2038.52,414.89 2046.67,406.73 cw(c2034.63,406.73) 2043.14,398.21 2024,379.07
  pour cut-out: 2019.72,441.65 2044.89,416.48 2036.73,408.33 cw(c2036.73,420.37) 2028.21,411.86 2009.07,431
Bottom Layer:
  pour cut-out: 2428,700 2218,700 2218,0 2428,0

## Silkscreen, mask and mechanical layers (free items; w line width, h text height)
Top Overlay:
  drawing of 555 lines, arcs and shapes, not listed
  text "RST" at 66,651 h60
  text "LED/25" at 2316,637 h40
  text "VIN" at 249,596.79 h40
  text "GND" at 340,596.79 h40
  text "IO4" at 451,596.79 h40
  text "IO0" at 550,596.79 h40
  text "IO2" at 651,596.79 h40
  text "IO15" at 740,596.79 h40
  text "IO13" at 839,596.79 h40
  text "IO12" at 941,596.79 h40
  text "IO14" at 1041,596.79 h40
  text "IO27" at 1146.18,596.79 h40
  text "IO26" at 1241,596.79 h40
  text "IO25" at 1340,596.79 h40
  text "IO33" at 1443,596.79 h40
  text "IO32" at 1544,596.79 h40
  text "IO35" at 1642,596.79 h40
  text "IO34" at 1741,596.79 h40
  text "PU" at 1857.18,597.03 h40
  text "VN" at 1953,596.79 h40
  text "VP" at 2055,596.79 h40
  text "GND" at 2140,596.79 h40
  text "R" at 726,513 h60
  text "T" at 580,511 h60
  text "PWR" at 1171,400 h60
  text "widora.io" at 808,162 h80
  text "SPIQ" at 1136.88,79.06 h40
  text "3V3" at 249,78.17 h40
  text "GND" at 342,77.99 h40
  text "3V3" at 447.07,77.97 h40
  text "IO16" at 540,77.99 h40
  text "IO17" at 644,77.99 h40
  text "HD" at 759,77.97 h40
  text "WP" at 853,77.97 h40
  text "CS0" at 945.64,77.99 h40
  text "CLK" at 1044,77.97 h40
  text "SPID" at 1241.14,77.99 h40
  text "IO5" at 1353,77.99 h40
  text "IO18" at 1444,77.99 h40
  text "IO23" at 1541.15,77.99 h40
  text "IO19" at 1640.15,77.99 h40
  text "IO22" at 1742.9,77.99 h40
  text "RXD0" at 1837.31,78.17 h40
  text "TXD0" at 1934.88,78.17 h40
  text "IO21" at 2043.12,77.99 h40
  text "GND" at 2141,77.99 h40
  text "LOAD" at 47,10 h60
Bottom Overlay:
  drawing of 571 lines, arcs and shapes, not listed
  text "-" at 639,382 h150
  text "BATTERY" at 460,336 h50
  text "+" at 636,247 h100
  text "What will you make?" at 1458,241 h70
  text "DESIGNED BY Mango" at 1235,142.5 h50
Top Solder:
  region: 2440,0.64 2440,593 2219,593 2219,0.64
  text "air" at 1955,496 h150
  text "V6.0" at 1968,138 h100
